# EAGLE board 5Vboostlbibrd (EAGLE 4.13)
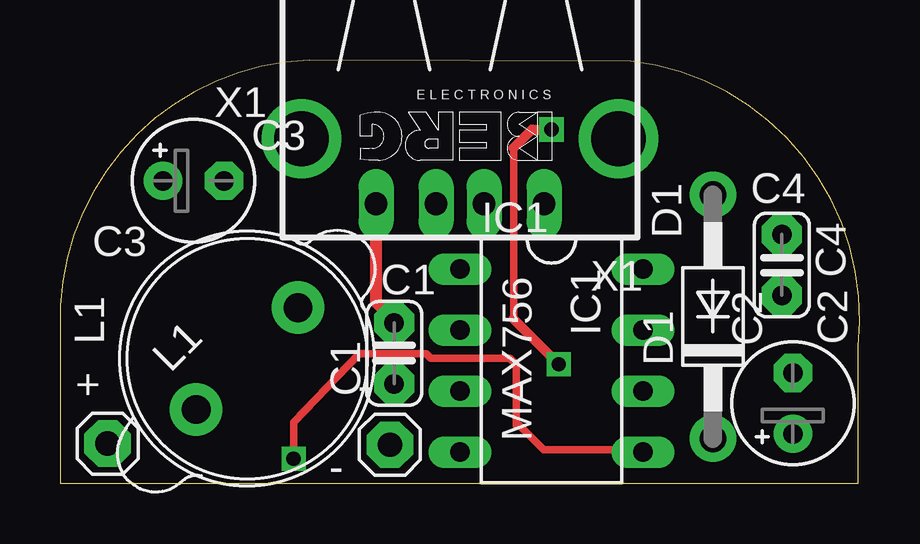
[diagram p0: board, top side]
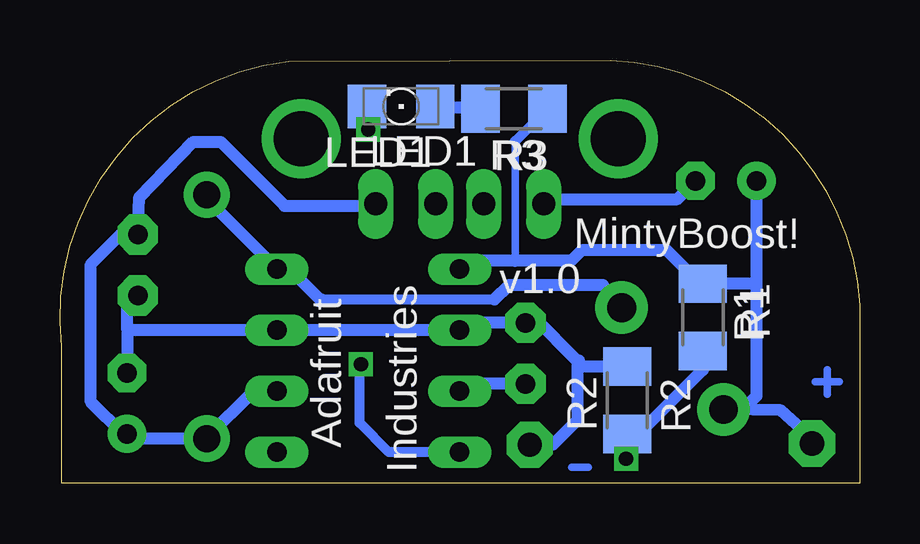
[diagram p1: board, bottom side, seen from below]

Size 33.32 x 17.63 mm. Coordinates in mm from the lower left corner, seen from the top.
Outline: 0,0 0,6.42 arc-90 10.38,17.63 23.79,17.58 arc-90 33.25,5.68 33.25,0
Outline: 0,0 33.25,0
Copper layers (1*16): Top 0.035mm / dielectric 1.5mm / Bottom 0.035mm
Design rules "default": minimum track width 12mil, minimum drill 24mil, track to track 10mil, track to pad 10mil, pad to pad 10mil, via to via 10mil, smd to smd 0mil, copper to edge 10mil, drill to drill 8mil, minimum pad ring 10mil, minimum via ring 8mil, stop-mask expansion 4mil, vias tented up to drill 0mil, thermal gap 10mil

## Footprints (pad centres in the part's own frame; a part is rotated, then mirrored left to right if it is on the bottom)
1X01 = drill 1.016 pad 1.93 octagon: 1 0,0
C025-024X044 = drill 0.813 pad 1.676 octagon: 1 -1.27,0; 2 1.27,0
E2,5-5 = drill 0.813 pad 1.6 round: + -1.27,0 | drill 0.813 pad 1.6 octagon: - 1.27,0
DO41-10 = drill 1.118 pad 1.93 round: A 5.08,0; C -5.08,0
DIL08 = drill 0.813 long: 1 -3.81,-3.81; 2 -1.27,-3.81; 3 1.27,-3.81; 4 3.81,-3.81; 5 3.81,3.81; 6 1.27,3.81; 7 -1.27,3.81; 8 -3.81,3.81
1800R = drill 1.2 pad 2.184 round: 1 -3,0; 2 3,0
1206 = smd 1.6 x 1.803: A -1.422,0; C 1.422,0
M1206 = smd 1.6 x 2: 1 -1.4,0; 2 1.4,0
PN87520 = drill 0.95 long: 1 -3.5,2.71; 2 -1,2.71; 3 1,2.71; 4 3.5,2.71 | drill 2.286 round: P$1 -6.604,0; P$2 6.604,0

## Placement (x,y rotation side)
+  [1X01]  1.99,1.65 0 top
-  [1X01]  13.75,1.6 0 top
C1  .1uF  [C025-024X044]  13.92,5.41 90 top
C2  100uF  [E2,5-5]  30.54,3.33 90 top
C3  100uF  [E2,5-5]  5.57,12.6 0 top
C4  .1uF  [C025-024X044]  30.08,9.1 270 top
D1  1N5817  [DO41-10]  27.21,6.94 90 top
IC1  MAX756  [DIL08]  20.48,5.11 270 top
L1  L1800R  [1800R]  7.8,5.19 45 top
LED1  [1206]  19.11,15.7 180 bottom
R1  100K  [M1206]  6.53,6.91 270 bottom
R2  110K  [M1206]  9.68,3.46 90 bottom
R3  [M1206]  14.41,15.6 180 bottom
X1  [PN87520]  16.67,14.35 180 top

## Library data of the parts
+ - = pinhead-ez
C1-C4 = rcl-ez
D1 IC1 L1 = usbbuck
LED1 = led
R1-R3 = rcl
X1 = con-berg

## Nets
GND: -.1 C1.2 C2.- C3.- C4.2 IC1.2 IC1.7 R2.2 X1.4
N$1: C1.1 IC1.3
N$2: +.1 C3.+ IC1.1 L1.1 R1.1 R3.1
N$3: C2.+ C4.1 D1.C IC1.6 X1.1
N$5: D1.A IC1.8 L1.2
N$6: IC1.4 LED1.C
N$9: IC1.5 R1.2 R2.1
N$10: LED1.A R3.2

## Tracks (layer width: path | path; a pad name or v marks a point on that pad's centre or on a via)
GND
  Top 0.508: C1.2 13.92,6.79 13.17,7.54 X1.4
  Bottom 0.508: -.1 12.78,1.6 11.76,2.62 11.76,5.11 | 11.76,5.11 13.54,6.89 13.75,6.68 C1.2 16.13,6.68 16.44,6.38 IC1.2 IC1.7 30.51,6.38 | X1.4 12.97,11.84 7.6,11.84 C3.- | 30.54,4.8 C2.- 30.51,4.63 30.51,6.38 | C4.2 30.31,7.6 30.51,7.34 30.51,6.38 | 11.76,5.11 11.69,5.11 11.69,4.86 R2.2
N$1
  Bottom 0.508: IC1.3 16.41,3.84 16.34,3.76 15.96,4.14 C1.1
N$2
  Bottom 0.305: 14.36,9.27 14.36,14.25
  Bottom 0.406: 14.36,9.27 14.36,9.22 | 14.36,14.25 R3.1
  Bottom 0.508: L1.1 4.87,3.06 4.3,3.63 4.3,8.31 | 4.3,8.31 C3.+ | +.1 1.99,1.86 3.29,3.03 L1.1 | L1.1 5.65,3.03 | IC1.1 16.67,8.84 16.59,8.77 16.08,9.27 14.36,9.27 12.02,9.27 11.59,9.71 8.03,9.71 6.64,8.31 R1.1 4.3,8.31
N$3
  Bottom 0.508: C2.+ 30.64,2.16 | C2.+ 30.33,1.86 D1.C 27.21,1.91 25.28,3.84 IC1.6 | X1.1 20.15,11.62 20.15,11.56 23.96,11.56 26.62,14.23 27.77,14.23 30.03,11.89 C4.1 30.79,10.37 32.03,9.12 32.03,3.38 30.69,2.03 30.66,2.06 C2.+
N$4
  Bottom 0.305: 1.86,4.22 0.84,4.22
N$5
  Bottom 0.406: 15.22,7.65 22.43,7.65 | L1.2 10.34,7.8 10.29,7.85 10.7,8.26
  Bottom 0.508: D1.A 27.26,12.02 27.31,11.97 24.29,8.94 IC1.8 23.75,8.92 22.48,7.65 22.43,7.65 | 15.22,7.65 14.61,8.26 10.7,8.26
N$6  (via drill 0.6)
  Top 0.305: 18.9,6.84 18.9,13.97
  Top 0.406: v20.78,4.96 18.9,6.84 | 18.9,13.97 19.66,14.73 v20.48,14.73
  Bottom 0.406: IC1.4 19.61,1.3 20.83,2.52 20.83,5.16 v20.78,4.96 | LED1.C 20.5,15.67 20.35,15.67 20.35,14.86 v20.48,14.73
N$7
  Bottom 0.305: 1.35,4.73 1.35,3.71
N$8
  Bottom 0.305: 11.31,0.66 11.99,0.66
N$9  (via drill 0.6)
  Top 0.305: IC1.5 24.19,1.4 20.15,1.4 19.13,2.42 19,2.42 19,4.96 18.75,5.21 15.45,5.21 15.27,5.39 12.48,5.39 9.73,2.54 v9.73,1.02
  Bottom 0.305: R2.1 9.7,2.42 9.73,2.42 v9.73,1.02
  Bottom 0.508: R1.2 6.53,4.73 8.84,2.42 9.33,2.42 9.38,2.36 9.45,2.44 R2.1
N$10
  Bottom 0.508: R3.2 15.86,15.65 17.63,15.65 LED1.A

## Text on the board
tPlace: X1 | C4 | C3 | D1 | C1 | L1 | IC1 | C2 | MAX756 | -
bPlace: R3 | LED1 | MintyBoost! | R1 | v1.0 | R2 | Adafruit | Industries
